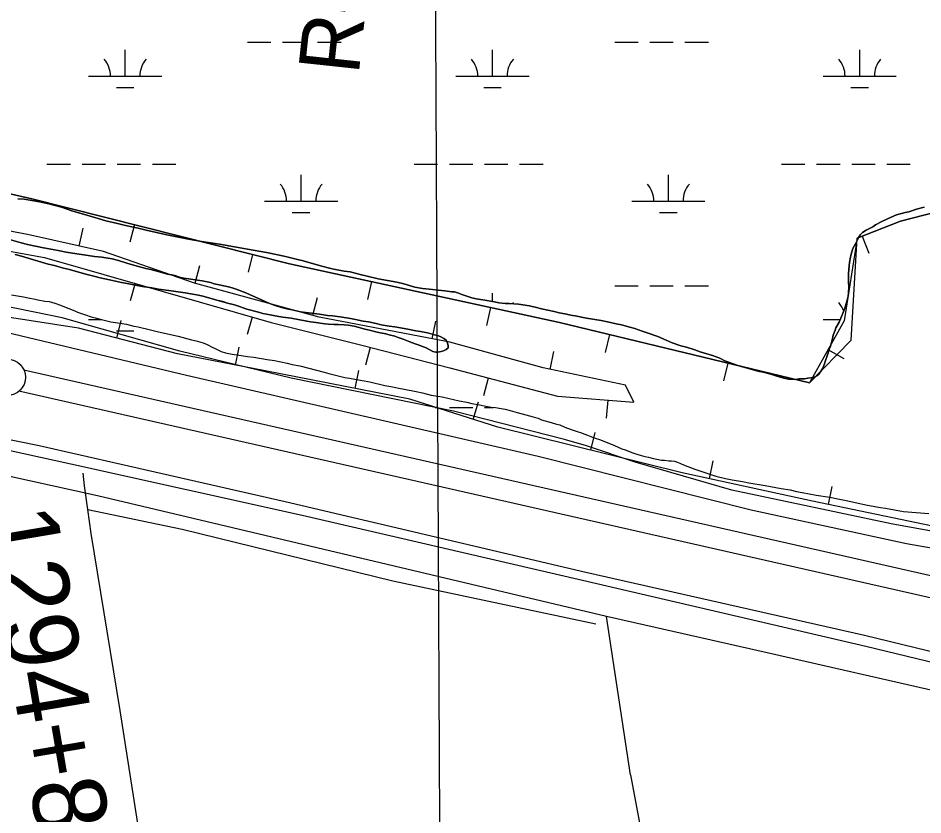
# Model space of a CAD drawing. Extents: x 3445503 to 3483459, y 540493 to 566012.
# Drawn here: x 3464890 to 3466127, y 547752 to 548842 of the extents above; entities that cross this region are included whole.
import ezdxf

# ---------------------------------------------------------------- set-up
doc = ezdxf.new("R2010")
doc.units = 0
for name, color, linetype in [('V-BORW-LINE', 7, 'Continuous'), ('V-DTCH-CNTR', 7, 'Continuous'), ('V-GRID-MAJR', 7, 'Continuous'), ('V-LEVE-TOET', 7, 'Continuous'), ('V-RIVR-RANG-IDEN', 7, 'Continuous'), ('V-ROAD-CNTR', 7, 'Continuous'), ('V-SITE-VEGE', 7, 'Continuous'), ('V-SURV-IDEN', 7, 'Continuous'), ('V-SURV-LINE', 7, 'Continuous'), ('V-TOPO-SHOR', 7, 'Continuous'), ('V-WETL-SWMP', 7, 'Continuous')]:
    doc.layers.add(name, color=color, linetype=linetype)

msp = doc.modelspace()

# ---------------------------------------------------------------- linework, layer by layer
at = {"layer": 'V-BORW-LINE'}
for p, q in [((3464973.7, 548529.8), (3464979.2, 548554.2)), ((3465049.2, 548559.2), (3465043.1, 548535)), ((3466043.8, 548543.3), (3466052.9, 548520)), ((3465210.7, 548518.4), (3465204.6, 548494.2)), ((3465132.2, 548479), (3465138.8, 548503.1)), ((3465050.2, 548479), (3465043.3, 548454.9)), ((3465373.1, 548481.3), (3465367.8, 548456.9)), ((3465292.9, 548435.2), (3465299.5, 548459.4)), ((3465535.9, 548445.9), (3465530.6, 548421.4)), ((3465025.2, 548403.9), (3465031.4, 548428.1)), ((3465210.3, 548432.9), (3465203.4, 548408.9)), ((3465456.4, 548402.9), (3465461.1, 548427.4)), ((3465698.4, 548408.9), (3465692.5, 548384.6)), ((3465187.6, 548367), (3465192.3, 548391.6)), ((3465371.6, 548391.3), (3465365.3, 548367.1)), ((3465617.5, 548361.1), (3465622.6, 548385.6)), ((3465997.1, 548388.3), (3466018.9, 548376.2)), ((3465860.3, 548369.9), (3465854.5, 548345.6)), ((3465351.1, 548335.2), (3465355.9, 548359.8)), ((3465532.8, 548349.4), (3465526.5, 548325.2)), ((3465512, 548293), (3465519.6, 548316.9)), ((3465696.1, 548319.4), (3465694.2, 548294.5)), ((3465673, 548250.7), (3465679, 548275)), ((3465835, 548211.8), (3465840.3, 548236.3)), ((3465997.9, 548176.7), (3466003, 548201.2))]:
    msp.add_line(p, q, dxfattribs=at)
for points in [[(3464489.9, 548724.2), (3464510.5, 548693.6), (3464646.3, 548654.7), (3464909.3, 548594.6), (3465261.4, 548505.7), (3465630.1, 548425.3), (3465971.9, 548343), (3466029, 548401.2), (3466037.2, 548540.7), (3466096.3, 548563.8), (3466193.8, 548589.2)], [(3466193.8, 548589.2), (3466096.3, 548563.8), (3466037.2, 548540.7), (3466019, 548427.8), (3465971.9, 548343), (3465630.1, 548425.3), (3465261.4, 548505.7), (3464909.3, 548594.6), (3464646.3, 548654.7), (3464510.5, 548693.6), (3464489.9, 548724.2)], [(3464775, 548541.6), (3464926.2, 548514.4), (3465088.8, 548467.9), (3465236.1, 548425.5), (3465360.1, 548394.3), (3465480.2, 548363.2), (3465627.5, 548324.6), (3465731.7, 548316.7), (3465720.4, 548339.9), (3465607.7, 548363.2), (3465480.2, 548398.3), (3465301.8, 548432.8), (3465131.3, 548479.3), (3465007.2, 548522.3), (3464903, 548545.6), (3464763.7, 548572.2)], [(3466161.7, 548142.2), (3465975.9, 548181.3), (3465798, 548219.8), (3465545.9, 548282.2), (3465425.8, 548320.7), (3465228.1, 548359.2), (3465108.1, 548382.4), (3464972.7, 548417.5), (3464875.8, 548432.8)]]:
    msp.add_lwpolyline(points, dxfattribs=at)
at = {"layer": 'V-DTCH-CNTR'}
for points in [[(3465030, 547894.9), (3464990.2, 548137), (3464985.7, 548169.8), (3464981.3, 548201.9), (3464979.4, 548219.4)], [(3464985.7, 548169.8), (3465114.5, 548142.7), (3465402.3, 548072.2), (3465679.8, 548013.3)], [(3465102.6, 547442.5), (3465057.9, 547714.3), (3465030, 547894.9)]]:
    msp.add_lwpolyline(points, dxfattribs=at)
at = {"layer": 'V-GRID-MAJR'}
msp.add_spline([(3465476.1, 545965.8), (3465445.3, 552023.3), (3465414.4, 558084.3), (3465383.6, 564145.3), (3465383.6, 564148.7)], degree=3, dxfattribs=at)
at = {"layer": 'V-LEVE-TOET'}
for points in [[(3466239.9, 548099), (3466104.5, 548122.7), (3465892.1, 548169), (3465600.9, 548242.3), (3465397.6, 548289.2), (3465120.7, 548352.9), (3464864, 548414), (3464590.4, 548469.8), (3464321.4, 548521.1), (3464021.1, 548576.2), (3463744.3, 548624.2), (3463488.3, 548672.3), (3463189.3, 548723.5), (3462887.7, 548781.2), (3462559.4, 548840.8), (3462324.3, 548867.5), (3462035.1, 548909.6), (3461900.3, 548919.6), (3461785.1, 548927.1), (3461709.6, 548931.9)], [(3463625.4, 548510.5), (3463879.5, 548460.5), (3464284, 548384.2), (3464566.7, 548329), (3464919.1, 548257.2), (3465255.3, 548180.7), (3465666.3, 548084.2), (3466046.8, 547998.1), (3466168.6, 547968.5), (3466187.5, 547962), (3466198.6, 547960.7), (3466216.2, 547956.2), (3466231.9, 547950.4), (3466441, 547902.2), (3466456.6, 547900.9), (3466471.1, 547904.1), (3466495.8, 547905.4), (3466511.5, 547899.6), (3466526.5, 547894.5), (3466580.5, 547875.7), (3466786.4, 547827.5), (3466931.9, 547797.1)]]:
    msp.add_lwpolyline(points, dxfattribs=at)
at = {"layer": 'V-ROAD-CNTR'}
msp.add_lwpolyline([(3467429.3, 547662), (3466960, 547773.3), (3466692.5, 547831.7), (3466423.7, 547891.6), (3466048.9, 547982.6), (3465661.7, 548072.5), (3465278.6, 548161.5), (3464962.5, 548231.9), (3464746.5, 548279.3), (3464560.4, 548315.9), (3464262.6, 548372.6), (3464037.8, 548415.3), (3463794.4, 548459.3)], dxfattribs=at)
at = {"layer": 'V-SITE-VEGE'}
for points in [[(3464889.9, 548594.4), (3464898.6, 548593.8), (3464919.7, 548590.4), (3464932.4, 548587.8), (3464941.1, 548585.5), (3464949.6, 548582.9), (3464964, 548578.1), (3464984.3, 548572.2), (3464999.7, 548567.4), (3465010.4, 548564.6), (3465026.2, 548560.6), (3465037.2, 548558), (3465054.5, 548554.3), (3465065.5, 548551.7), (3465093.7, 548545.4), (3465123.4, 548539.4), (3465141.4, 548536.1), (3465147.3, 548535.1), (3465165.6, 548532.6), (3465193.9, 548527.3), (3465204, 548525.7), (3465229.9, 548521.1), (3465245.4, 548518.1), (3465255.8, 548515.7), (3465270.5, 548511.8), (3465279.9, 548509.7), (3465303.6, 548502.8), (3465317.5, 548499.1), (3465322, 548498.1), (3465335.9, 548495.7), (3465344.3, 548494.5), (3465357.7, 548491.2), (3465367.2, 548488.6), (3465382.3, 548484.9), (3465407.7, 548480.5), (3465417.7, 548478.1), (3465432.7, 548473.8), (3465442.8, 548471.8), (3465456.7, 548470.3), (3465464.3, 548469.4), (3465473.7, 548468.7), (3465483.1, 548467.4), (3465486.5, 548467.1), (3465492.4, 548465.5), (3465496.9, 548463.7), (3465510.5, 548459.2), (3465516.3, 548457.8), (3465525.3, 548456.3), (3465541.6, 548453.5), (3465547.5, 548452.3), (3465555.9, 548451.5), (3465561.3, 548451.4), (3465574.2, 548450.4), (3465589, 548448.1), (3465598.6, 548446), (3465605.4, 548444.3), (3465622.8, 548440.5), (3465629.9, 548438.7), (3465637.3, 548437.1), (3465648, 548435), (3465651.7, 548434.4), (3465667.3, 548431.4), (3465687.3, 548428.1), (3465695.8, 548426.5), (3465707.5, 548423.7), (3465715, 548422.1), (3465726.2, 548419.1), (3465733.2, 548417.1), (3465743.2, 548413.5), (3465750.2, 548411.3), (3465764.5, 548406.3), (3465776, 548401.1), (3465784.3, 548397.5), (3465796.2, 548393.4)], [(3465796.2, 548393.4), (3465803.7, 548391.6), (3465815, 548388.2), (3465822.4, 548385.5), (3465839.1, 548380.4), (3465849.3, 548376.5), (3465856.2, 548373.2), (3465867.6, 548368.8), (3465875.1, 548366.2), (3465890.2, 548362.2), (3465901.1, 548358.9), (3465908.5, 548357.4), (3465919.1, 548354.6), (3465926, 548352.4), (3465936.8, 548349.4), (3465943.3, 548348.1), (3465951.8, 548347.7), (3465957.5, 548348.3), (3465965, 548348.3), (3465969.7, 548349.2), (3465977.3, 548350.2), (3465982, 548352.6), (3465984.7, 548354.6), (3465987.9, 548359.3), (3465989.9, 548363), (3465992.2, 548369.1), (3465993.8, 548373.6), (3465995.8, 548380), (3465997.2, 548383.9), (3465999.1, 548389.7), (3466000.4, 548392.9), (3466001.7, 548397.9), (3466002.9, 548401.4), (3466004.4, 548408), (3466006.9, 548415), (3466008, 548418), (3466012.3, 548426), (3466014.8, 548431.5), (3466018.7, 548441.3), (3466020.1, 548445.2), (3466022.1, 548451.4), (3466023.3, 548455.8), (3466024.6, 548461.3), (3466025.1, 548465.5), (3466025.4, 548474.2), (3466025.1, 548481.1), (3466025.1, 548492.5), (3466025.9, 548502.7), (3466026.5, 548507.5), (3466027.9, 548514.6), (3466028.7, 548518.6), (3466030.9, 548526.4), (3466034.6, 548532.9), (3466036.4, 548536.4), (3466038.7, 548541.8), (3466041.3, 548545.4), (3466044.3, 548548.3), (3466049.2, 548551.8), (3466052.9, 548553.3), (3466058.2, 548556.2), (3466062.1, 548558.7), (3466070.9, 548563.3), (3466083.4, 548569.6), (3466090.6, 548572.4), (3466102.8, 548575.6), (3466107.6, 548576.8), (3466118.2, 548580.1), (3466128.4, 548583.2)], [(3465468.1, 548405.7), (3465465, 548407.2), (3465459.5, 548408.7), (3465449.8, 548411.2), (3465440.4, 548413), (3465433.7, 548414), (3465423.1, 548416.2), (3465405.1, 548419.5), (3465397.6, 548420.5), (3465386.4, 548422.4), (3465379.5, 548424), (3465369, 548426.2), (3465362.1, 548427.3), (3465351.6, 548429.6), (3465344.6, 548430.9), (3465330.4, 548433.2), (3465320, 548434.4), (3465313.2, 548435.1), (3465302.2, 548436.6), (3465276.3, 548440.2), (3465265, 548442.7), (3465257.5, 548444), (3465250.1, 548445.8), (3465240.1, 548449.3), (3465232.8, 548452), (3465222.8, 548456.2), (3465201.5, 548466), (3465188.3, 548470.9), (3465182.9, 548472.7), (3465177.8, 548474.2), (3465165.3, 548477), (3465158.1, 548478.3), (3465153.4, 548480), (3465146.6, 548481.6), (3465142, 548482.5), (3465116.8, 548485.9), (3465112.4, 548487), (3465104.4, 548489.5), (3465100.2, 548490.5), (3465094.3, 548491.5), (3465081.8, 548494.9), (3465071.9, 548497.8), (3465065.1, 548499.2), (3465054.7, 548502.1), (3465046.5, 548504.1), (3465039.1, 548506.7), (3465027.4, 548510.1), (3465018.8, 548512.3), (3465004.6, 548514.7), (3464994.8, 548515.8), (3464980.4, 548517.7), (3464970.5, 548519.1), (3464956.2, 548521.6), (3464947.2, 548523.5), (3464938, 548525.1), (3464925, 548527.5), (3464903.4, 548532.2), (3464894.5, 548534.4), (3464872.3, 548540.5)], [(3464886.3, 548518.4), (3464895, 548516), (3464908.5, 548511.9), (3464931.3, 548505.3), (3464940.1, 548503.2), (3464952.6, 548499.7), (3464960.5, 548497.7), (3464981.2, 548492), (3464993.8, 548488.7), (3465002.5, 548486.3), (3465015.4, 548483.7), (3465031.8, 548480.1), (3465039.4, 548478.7), (3465051, 548476.3), (3465059.7, 548474.8), (3465073.3, 548472.8), (3465082.4, 548471.1), (3465096.2, 548469), (3465118.6, 548466), (3465126.5, 548464.6), (3465136.8, 548462.6), (3465142.8, 548461.3), (3465151, 548459.3), (3465161.8, 548456.1), (3465170.3, 548453.8), (3465176.3, 548452), (3465185.9, 548449.4), (3465192.7, 548447.2), (3465203, 548443.8), (3465218.7, 548439.4), (3465224.6, 548437.9), (3465230, 548436.9), (3465246.6, 548433.5), (3465252.3, 548432.5), (3465263.5, 548431.1), (3465284.8, 548427.2), (3465289.9, 548426.5), (3465297.4, 548425.2), (3465309.4, 548423.7), (3465314.5, 548423.3), (3465322.3, 548422.8), (3465327.9, 548422.7), (3465336, 548422.3), (3465341.6, 548421.7), (3465349.8, 548420.2), (3465359.6, 548417.7), (3465364.1, 548416.3), (3465370.5, 548415), (3465380.9, 548412.4), (3465385.7, 548411.1), (3465392.7, 548409.7), (3465397.6, 548408.6), (3465405, 548406.6), (3465409.7, 548404.8), (3465416.6, 548402.5), (3465425.9, 548398.9), (3465432.9, 548396.3), (3465437.2, 548394.9), (3465447.8, 548390.9), (3465457.1, 548385.8), (3465461, 548385), (3465464.1, 548384.7), (3465468.7, 548385.6), (3465471.6, 548386.6), (3465475.1, 548388.4), (3465478.1, 548390.7), (3465478.1, 548394), (3465477.1, 548397.3), (3465475.3, 548401.3), (3465472, 548403.7), (3465468.1, 548405.7)]]:
    msp.add_lwpolyline(points, dxfattribs=at)
at = {"layer": 'V-SURV-LINE'}
for points in [[(3464898.2, 548360.7), (3467449, 547782.1)], [(3464898.2, 548360.7), (3467449, 547782.1)], [(3467442.4, 547752.8), (3464891.5, 548331.4)], [(3467442.4, 547752.8), (3464891.5, 548331.4)]]:
    msp.add_lwpolyline(points, dxfattribs=at)
msp.add_circle((3464875.4, 548350.5), 25, dxfattribs=at)
at = {"layer": 'V-TOPO-SHOR'}
msp.add_line((3465727.1, 547807.2), (3465694.4, 548023.5), dxfattribs=at)
for points in [[(3465694.4, 548023.5), (3464998.7, 548188.3), (3464715.6, 548250.8)], [(3466708.6, 547790), (3466561.5, 547826.5), (3466437, 547853.3), (3466157.9, 547918.1), (3465914, 547973.9), (3465694.4, 548023.5)], [(3465727.1, 547807.2), (3465783.6, 547505.5), (3465788.9, 547477.6), (3465867.1, 547030), (3465918.3, 546736.6)]]:
    msp.add_lwpolyline(points, dxfattribs=at)
at = {"layer": 'V-WETL-SWMP'}
for p, q in [((3465036.7, 548762), (3465036.7, 548798)), ((3465203.7, 548808.4), (3465235.7, 548808.4)), ((3465251.7, 548808.4), (3465283.7, 548808.4)), ((3465299.7, 548808.4), (3465331.7, 548808.4)), ((3465538.6, 548762), (3465538.6, 548798)), ((3465705.6, 548808.4), (3465737.6, 548808.4)), ((3465753.6, 548808.4), (3465785.6, 548808.4)), ((3465801.6, 548808.4), (3465833.6, 548808.4)), ((3466040.5, 548762), (3466040.5, 548798)), ((3464986.7, 548762), (3465086.7, 548762)), ((3465488.6, 548762), (3465588.6, 548762)), ((3465990.5, 548762), (3466090.5, 548762)), ((3465024.7, 548746.5), (3465048.7, 548746.5)), ((3465526.6, 548746.5), (3465550.6, 548746.5)), ((3466028.5, 548746.5), (3466052.5, 548746.5)), ((3464929.8, 548641.9), (3464961.8, 548641.9)), ((3464977.8, 548641.9), (3465009.8, 548641.9)), ((3465025.8, 548641.9), (3465057.8, 548641.9)), ((3465073.8, 548641.9), (3465105.8, 548641.9)), ((3465431.7, 548641.9), (3465463.7, 548641.9)), ((3465479.7, 548641.9), (3465511.7, 548641.9)), ((3465527.7, 548641.9), (3465559.7, 548641.9)), ((3465575.7, 548641.9), (3465607.7, 548641.9)), ((3465933.6, 548641.9), (3465965.6, 548641.9)), ((3465981.6, 548641.9), (3466013.6, 548641.9)), ((3466029.6, 548641.9), (3466061.6, 548641.9)), ((3466077.6, 548641.9), (3466109.6, 548641.9)), ((3465277.1, 548591.2), (3465277.1, 548627.2)), ((3465779, 548591.2), (3465779, 548627.2)), ((3465227.1, 548591.2), (3465327.1, 548591.2)), ((3465729, 548591.2), (3465829, 548591.2)), ((3465265.1, 548575.7), (3465289.1, 548575.7)), ((3465767, 548575.7), (3465791, 548575.7)), ((3465705.6, 548475.7), (3465737.6, 548475.7)), ((3465753.6, 548475.7), (3465785.6, 548475.7)), ((3465801.6, 548475.7), (3465833.6, 548475.7)), ((3465538.6, 548454), (3465538.6, 548465.3)), ((3464986.7, 548429.3), (3465004.5, 548429.3)), ((3465990.5, 548429.3), (3466013.8, 548429.3)), ((3465024.7, 548413.9), (3465048.7, 548413.9)), ((3465460.4, 548309.2), (3465463.7, 548309.2)), ((3465479.7, 548309.2), (3465511.7, 548309.2)), ((3465527.7, 548309.2), (3465540.2, 548309.2))]:
    msp.add_line(p, q, dxfattribs=at)
for points in [[(3466159.1, 548136.3), (3466085.7, 548149.8), (3465865.6, 548196.4), (3465733.5, 548234.5), (3465667.2, 548256.8), (3465636.9, 548265.5), (3465485.2, 548304.2), (3465263.4, 548349.2), (3465111.4, 548386.2), (3464950.4, 548432), (3464805.3, 548461.4), (3464564.5, 548504.3), (3464434.4, 548536.4), (3464216.1, 548574.4), (3464062.8, 548605.8), (3463861, 548637), (3463745.7, 548660.1), (3463705.1, 548670.3)], [(3465667.3, 548431.4), (3465651.7, 548434.4), (3465648, 548435), (3465637.3, 548437.1), (3465629.9, 548438.7), (3465622.8, 548440.5), (3465605.4, 548444.3), (3465598.6, 548446), (3465589, 548448.1), (3465574.2, 548450.4), (3465561.3, 548451.4), (3465555.9, 548451.5), (3465547.5, 548452.3), (3465541.6, 548453.5), (3465525.3, 548456.3), (3465516.3, 548457.8), (3465510.5, 548459.2), (3465496.9, 548463.7), (3465492.4, 548465.5), (3465486.5, 548467.1), (3465483.1, 548467.4), (3465473.7, 548468.7), (3465464.3, 548469.4), (3465456.7, 548470.3), (3465442.8, 548471.8), (3465432.7, 548473.8), (3465417.7, 548478.1), (3465407.7, 548480.5), (3465382.3, 548484.9), (3465367.2, 548488.6), (3465357.7, 548491.2), (3465344.3, 548494.5), (3465335.9, 548495.7), (3465322, 548498.1), (3465317.5, 548499.1), (3465303.6, 548502.8), (3465279.9, 548509.7), (3465270.5, 548511.8), (3465255.8, 548515.7), (3465245.4, 548518.1), (3465229.9, 548521.1), (3465204, 548525.7), (3465193.9, 548527.3), (3465165.6, 548532.6), (3465147.3, 548535.1), (3465141.4, 548536.1), (3465123.4, 548539.4), (3465093.7, 548545.4), (3465065.5, 548551.7), (3465054.5, 548554.3), (3465037.2, 548558), (3465026.2, 548560.6), (3465010.4, 548564.6), (3464999.7, 548567.4), (3464984.3, 548572.2), (3464964, 548578.1), (3464949.6, 548582.9), (3464941.1, 548585.5), (3464932.4, 548587.8), (3464919.7, 548590.4), (3464898.6, 548593.8), (3464889.9, 548594.4)], [(3466128.4, 548583.2), (3466118.2, 548580.1), (3466107.6, 548576.8), (3466102.8, 548575.6), (3466090.6, 548572.4), (3466083.4, 548569.6), (3466070.9, 548563.3), (3466062.1, 548558.7), (3466058.2, 548556.2), (3466052.9, 548553.3), (3466049.2, 548551.8), (3466044.3, 548548.3), (3466041.3, 548545.4), (3466038.7, 548541.8), (3466036.4, 548536.4), (3466034.6, 548532.9), (3466030.9, 548526.4), (3466028.7, 548518.6), (3466027.9, 548514.6), (3466026.5, 548507.5), (3466025.9, 548502.7), (3466025.1, 548492.5), (3466025.1, 548481.1), (3466025.4, 548474.2), (3466025.1, 548465.5), (3466024.6, 548461.3), (3466023.3, 548455.8), (3466022.1, 548451.4), (3466020.1, 548445.2), (3466018.7, 548441.3), (3466014.8, 548431.5), (3466012.3, 548426), (3466008, 548418), (3466006.9, 548415), (3466004.4, 548408), (3466002.9, 548401.4), (3466001.7, 548397.9), (3466000.4, 548392.9), (3465999.1, 548389.7), (3465997.2, 548383.9), (3465995.8, 548380), (3465993.8, 548373.6), (3465992.2, 548369.1), (3465989.9, 548363), (3465987.9, 548359.3), (3465984.7, 548354.6), (3465982, 548352.6), (3465977.3, 548350.3), (3465969.7, 548349.2), (3465965, 548348.3), (3465957.5, 548348.3), (3465951.8, 548347.7), (3465943.3, 548348.1), (3465936.8, 548349.4), (3465926, 548352.4), (3465919.1, 548354.6), (3465908.5, 548357.4), (3465901.1, 548358.9), (3465890.2, 548362.2), (3465875.1, 548366.2), (3465867.6, 548368.8), (3465856.2, 548373.2), (3465849.3, 548376.5), (3465839.1, 548380.4), (3465822.4, 548385.5), (3465815, 548388.2), (3465803.7, 548391.6), (3465796.2, 548393.4), (3465784.3, 548397.5), (3465776, 548401.1), (3465764.5, 548406.3), (3465750.2, 548411.3), (3465743.2, 548413.5), (3465733.2, 548417.1), (3465726.2, 548419.1), (3465715, 548422.1), (3465707.5, 548423.7), (3465695.8, 548426.5), (3465687.3, 548428.1), (3465667.3, 548431.4)], [(3464872.3, 548540.5), (3464894.5, 548534.4), (3464903.4, 548532.2), (3464925, 548527.5), (3464938, 548525.1), (3464947.2, 548523.5), (3464956.2, 548521.6), (3464970.5, 548519.1), (3464980.4, 548517.7), (3464994.8, 548515.8), (3465004.6, 548514.7), (3465018.8, 548512.3), (3465027.4, 548510.1), (3465039.1, 548506.7), (3465046.5, 548504.1), (3465054.7, 548502.1), (3465065.1, 548499.2), (3465071.9, 548497.8), (3465081.8, 548494.9), (3465094.3, 548491.5), (3465100.2, 548490.5), (3465104.4, 548489.5), (3465112.4, 548487), (3465116.8, 548485.9), (3465142, 548482.5), (3465146.6, 548481.6), (3465153.4, 548480), (3465158.1, 548478.3), (3465165.3, 548477), (3465177.8, 548474.2), (3465182.9, 548472.7), (3465188.3, 548470.9), (3465201.5, 548466), (3465222.8, 548456.2), (3465232.8, 548452), (3465240.1, 548449.3), (3465250.1, 548445.8), (3465257.5, 548444), (3465265, 548442.7), (3465276.3, 548440.2), (3465302.2, 548436.6), (3465313.2, 548435.1), (3465320, 548434.4), (3465330.4, 548433.2), (3465344.6, 548430.9), (3465351.6, 548429.6), (3465362.1, 548427.3), (3465369, 548426.2), (3465379.5, 548424), (3465386.4, 548422.4), (3465397.6, 548420.5), (3465405.1, 548419.5), (3465423.1, 548416.2), (3465433.7, 548414), (3465440.4, 548413), (3465449.8, 548411.2), (3465459.5, 548408.7), (3465465, 548407.2), (3465468.1, 548405.7), (3465472, 548403.7), (3465475.3, 548401.3), (3465477.1, 548397.3), (3465478.1, 548394), (3465478.1, 548390.7), (3465475.1, 548388.4), (3465471.6, 548386.6), (3465468.7, 548385.6), (3465464.1, 548384.7), (3465461, 548385), (3465457.1, 548385.8), (3465447.8, 548390.9), (3465437.2, 548394.9), (3465432.9, 548396.3), (3465425.9, 548398.9), (3465416.6, 548402.5), (3465409.7, 548404.8), (3465405, 548406.6), (3465397.6, 548408.6), (3465392.7, 548409.7), (3465385.7, 548411.1), (3465380.9, 548412.4), (3465370.5, 548415), (3465364.1, 548416.3), (3465359.6, 548417.7), (3465349.8, 548420.2), (3465341.6, 548421.7), (3465336, 548422.3), (3465327.9, 548422.7)], [(3465327.9, 548422.7), (3465322.3, 548422.8), (3465314.5, 548423.3), (3465309.4, 548423.7), (3465297.4, 548425.2), (3465289.9, 548426.5), (3465284.8, 548427.2), (3465263.5, 548431.1), (3465252.3, 548432.5), (3465246.6, 548433.5), (3465230, 548436.9), (3465224.6, 548437.9), (3465218.7, 548439.4), (3465203, 548443.8), (3465192.7, 548447.2), (3465185.9, 548449.4), (3465176.3, 548452), (3465170.3, 548453.9), (3465161.8, 548456.1), (3465151, 548459.3), (3465142.8, 548461.3), (3465136.8, 548462.6), (3465126.5, 548464.6), (3465118.6, 548466), (3465096.2, 548469), (3465082.4, 548471.1), (3465073.3, 548472.8), (3465059.7, 548474.8), (3465051, 548476.3), (3465039.4, 548478.7), (3465031.8, 548480.1), (3465015.4, 548483.7), (3465002.5, 548486.3), (3464993.8, 548488.7), (3464981.2, 548492), (3464960.5, 548497.7), (3464952.6, 548499.7), (3464940.1, 548503.2), (3464931.3, 548505.3), (3464908.5, 548511.9), (3464895, 548516), (3464886.3, 548518.4)], [(3464881.1, 548463), (3464897.5, 548460.4), (3464904, 548459), (3464913.5, 548457.2), (3464917.4, 548456.6), (3464926.7, 548454.6), (3464932.6, 548453.9), (3464935.9, 548453.3), (3464940.7, 548451.9), (3464948.1, 548449), (3464951.6, 548447.8), (3464967.7, 548441.4), (3464971.6, 548439.6), (3464982.5, 548435.9), (3464990.1, 548433.2), (3464995.7, 548431.6), (3465004.4, 548429.3), (3465017.3, 548426.3), (3465023.4, 548425.2), (3465038.7, 548422.9), (3465048.4, 548420.6), (3465054.5, 548419.3), (3465071.4, 548415.4), (3465082.3, 548412.7), (3465108.9, 548406.8), (3465127.1, 548401.8), (3465133.8, 548400.3), (3465143.3, 548397.4), (3465148.5, 548395.5), (3465155.4, 548391.9), (3465160.4, 548389.2), (3465167.9, 548385.7), (3465173.7, 548384.1), (3465182.7, 548382.3), (3465189.1, 548381.1), (3465204, 548378.9), (3465212.6, 548378), (3465230.9, 548374.9), (3465240.7, 548373.5), (3465258, 548369.9), (3465265, 548368.2), (3465275.3, 548366), (3465308.5, 548357.3), (3465314.9, 548355.8), (3465336.8, 548350.4), (3465343.3, 548349.1), (3465360.4, 548346.1), (3465371.1, 548344.1), (3465391.6, 548339.4), (3465399.7, 548338), (3465410.7, 548335.8), (3465417.8, 548334.3), (3465434.2, 548331.1), (3465442.9, 548329.1), (3465454.7, 548326.2), (3465469.9, 548323.7), (3465493.3, 548318.4), (3465503.6, 548316.4)], [(3465503.6, 548316.4), (3465510.5, 548314.8), (3465520.7, 548312.8), (3465527.1, 548311.4), (3465536.8, 548309.5), (3465542.9, 548309), (3465550.7, 548307.7), (3465555.8, 548306.7), (3465562.6, 548305.1), (3465572.5, 548302.2), (3465584.1, 548299.2), (3465594.2, 548296.4), (3465597.4, 548295.4), (3465601.2, 548294.4), (3465605.4, 548292.3), (3465619, 548288.6), (3465626.1, 548286.5), (3465630.5, 548285.5), (3465637.5, 548282.4), (3465646.3, 548279.1), (3465655.5, 548275.8), (3465658.9, 548274.8), (3465664.6, 548272.8), (3465668.5, 548271.4), (3465677.7, 548267.8), (3465686.4, 548264.9), (3465705.2, 548257.1), (3465715.4, 548252.8), (3465720, 548251.5), (3465730.2, 548247.3), (3465736.1, 548245.6), (3465740.4, 548244.2), (3465746.9, 548242.4), (3465751.8, 548241.4), (3465758.6, 548239.6), (3465763.3, 548238.4), (3465769.4, 548237.4), (3465773.6, 548237), (3465779.7, 548236.5), (3465783.4, 548236.3), (3465787.2, 548236), (3465791.4, 548234.5), (3465799.8, 548231), (3465815.2, 548225.1), (3465835.5, 548217.9), (3465843.9, 548215.5), (3465856.9, 548212.3), (3465866, 548210.5), (3465880.1, 548208.1), (3465889.1, 548206.2), (3465911.2, 548202.6), (3465933.3, 548198.5), (3465945.6, 548196.5), (3465953.9, 548194.5), (3465961.6, 548192.9), (3465981.1, 548189.2), (3465999.6, 548186.7), (3466010.4, 548184.4), (3466017.3, 548183.1), (3466024.2, 548181.4), (3466034.2, 548179.4), (3466051.1, 548175.8), (3466068.9, 548172.4), (3466075.9, 548171.4), (3466100.1, 548166.8), (3466134.7, 548164.1)]]:
    msp.add_lwpolyline(points, dxfattribs=at)
for centre, start, end in [((3464981.4, 548762.4), 359.2282, 40.7718), ((3465091.9, 548762.4), 139.2282, 180.7718), ((3465483.3, 548762.4), 359.2282, 40.7718), ((3465593.8, 548762.4), 139.2282, 180.7718), ((3465985.2, 548762.4), 359.2282, 40.7718), ((3466095.7, 548762.4), 139.2282, 180.7718), ((3465221.9, 548591.6), 359.2282, 40.7718), ((3465332.4, 548591.6), 139.2282, 180.7718), ((3465723.8, 548591.6), 359.2282, 40.7718), ((3465834.3, 548591.6), 139.2282, 180.7718), ((3465593.8, 548429.8), 139.2282, 142.8682), ((3465985.2, 548429.8), 18.7212, 40.7718)]:
    msp.add_arc(centre, 35.2, start, end, dxfattribs=at)

# ---------------------------------------------------------------- texts
at = {"layer": 'V-RIVR-RANG-IDEN'}
msp.add_text('R-151.3', height=83, rotation=83.8838, dxfattribs=at).set_placement((3465355.7, 548762.8))
at = {"layer": 'V-SURV-IDEN'}
msp.add_text('1294+89.9', height=100, rotation=279.6753, dxfattribs=at).set_placement((3464842.3, 548165.7))

doc.saveas('drawing.dxf')
